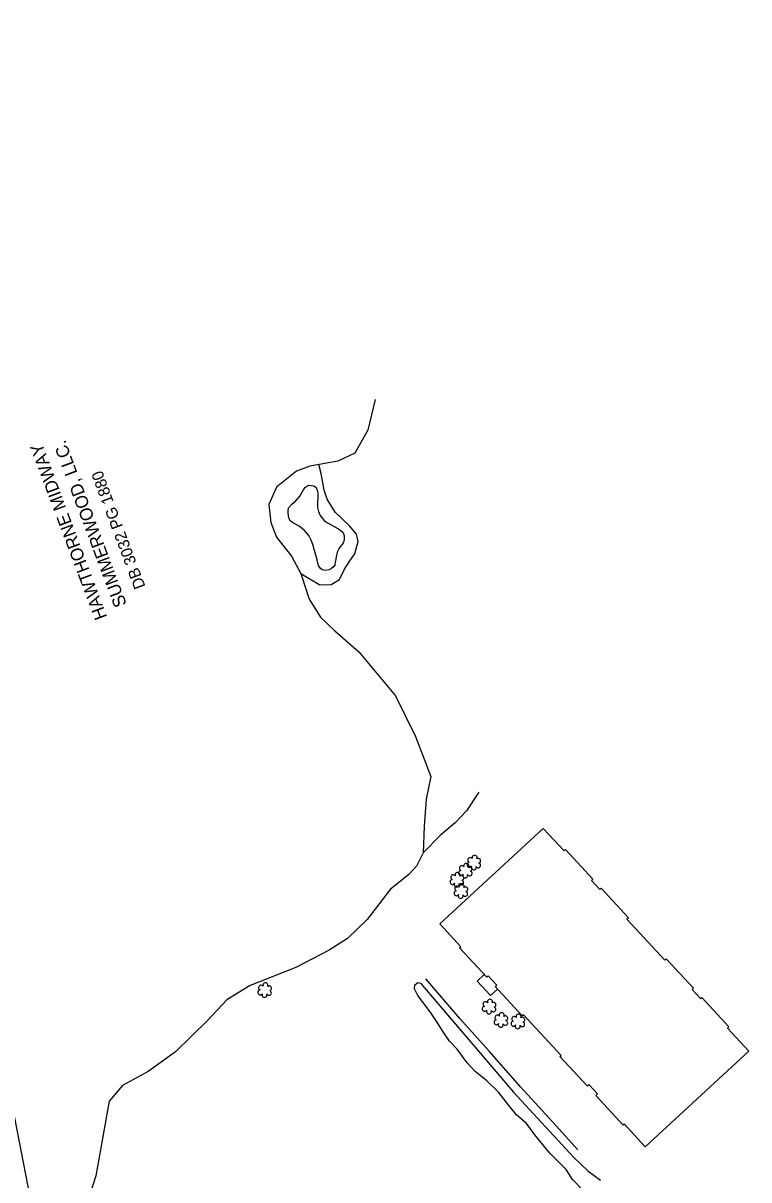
# Model space of a CAD drawing. Extents: x 1611576 to 1617186, y 899279 to 905462.
# Drawn here: x 1616361.3 to 1616645.4, y 903835.4 to 904288.3 of the extents above; entities that cross this region are included whole.
import ezdxf

# ---------------------------------------------------------------- set-up
doc = ezdxf.new("R2010")
doc.units = 0
for name, color, linetype in [('Exist Building', 7, 'Continuous'), ('Exist Other Culture Area Outline', 7, 'Continuous'), ('Exist Property Deed Book Text', 7, 'Continuous'), ('Exist Property Owner Text', 7, 'Continuous'), ('Exist Vegetation Hedge Row', 7, 'Continuous'), ('Exist Vegetation Shrub CELL', 7, 'Continuous'), ('Exist Vegetation Woods Line', 7, 'Continuous')]:
    doc.layers.add(name, color=color, linetype=linetype)

msp = doc.modelspace()

# ---------------------------------------------------------------- linework, layer by layer
at = {"layer": 'Exist Building'}
msp.add_lwpolyline([(1616645.44, 903885.78), (1616604.9, 903848.36), (1616596.66, 903857.28), (1616596.19, 903856.85), (1616585.49, 903868.45), (1616586.16, 903869.08), (1616582.89, 903872.63), (1616582.26, 903872.04), (1616571.49, 903883.71), (1616571.92, 903884.11), (1616557.21, 903900.05), (1616556.71, 903899.59), (1616546.07, 903911.11), (1616546.7, 903911.69), (1616543.39, 903915.27), (1616542.8, 903914.72), (1616532.18, 903926.23), (1616532.68, 903926.69), (1616524.44, 903935.63), (1616564.96, 903973.03), (1616573.06, 903964.25), (1616573.59, 903964.74), (1616584.34, 903953.09), (1616583.87, 903952.66), (1616587.13, 903949.13), (1616587.64, 903949.6), (1616598.3, 903938.04), (1616597.68, 903937.47), (1616612.48, 903921.42), (1616613.07, 903921.97), (1616623.74, 903910.41), (1616623.23, 903909.94), (1616626.58, 903906.32), (1616627.06, 903906.77), (1616637.66, 903895.28), (1616637.13, 903894.79)], close=True, dxfattribs=at)
msp.add_lwpolyline([(1616578.51, 903847.14), (1616569.84, 903856.72), (1616563.03, 903864.13), (1616555.97, 903871.79), (1616543.71, 903885.76), (1616532.29, 903898.62), (1616518.92, 903914.17)], dxfattribs=at)
at = {"layer": 'Exist Other Culture Area Outline'}
msp.add_lwpolyline([(1616476.65, 904102.98), (1616476.49, 904100.42), (1616476.54, 904098.64), (1616476.91, 904097.1), (1616477.59, 904095.58), (1616478.45, 904094.38), (1616479.34, 904093.41), (1616480.23, 904092.84), (1616481.24, 904092.29), (1616483.12, 904091.27), (1616484.75, 904090.36), (1616486.41, 904089.04), (1616486.74, 904088.47), (1616486.99, 904087.54), (1616486.95, 904086.53), (1616486.92, 904085.85), (1616486.61, 904084.78), (1616486.25, 904084.14), (1616485.67, 904083.61), (1616485.01, 904082.75), (1616484.27, 904081.13), (1616483.89, 904079.42), (1616483.77, 904078.37), (1616483.42, 904077.35), (1616483.28, 904076.15), (1616482.81, 904075.44), (1616482.08, 904074.79), (1616481.14, 904074.27), (1616479.66, 904074.05), (1616478.89, 904074.16), (1616478.33, 904074.28), (1616477.59, 904074.94), (1616476.98, 904075.92), (1616476.37, 904078.15), (1616475.38, 904081.88), (1616474.67, 904084.17), (1616474.05, 904085.93), (1616473.08, 904087.65), (1616471.48, 904089.65), (1616469.39, 904091.41), (1616467.16, 904092.53), (1616466, 904093.36), (1616465.47, 904094.19), (1616465.17, 904095.33), (1616464.99, 904096.72), (1616465.09, 904097.78), (1616465.3, 904098.64), (1616466.5, 904099.97), (1616467.87, 904101.12), (1616469.64, 904103.12), (1616471.18, 904105.87), (1616471.86, 904106.67), (1616472.61, 904107.17), (1616473.19, 904107.36), (1616474.11, 904107.32), (1616475.09, 904107.12), (1616475.75, 904106.68), (1616476.11, 904106.17), (1616476.6, 904105.02), (1616476.7, 904104.28), (1616476.71, 904103.33)], close=True, dxfattribs=at)
msp.add_lwpolyline([(1616546.98, 903910.12), (1616544.31, 903907.64), (1616539.09, 903913.26), (1616541.81, 903915.79)], dxfattribs=at)
at = {"layer": 'Exist Vegetation Hedge Row'}
for points in [[(1616469.99, 904072.86), (1616477.49, 904068.39), (1616481.83, 904068.54), (1616485.13, 904070.53), (1616487.1, 904074.59), (1616489.24, 904077.74), (1616491.2, 904080.59), (1616492.5, 904085.37), (1616491.82, 904088.27), (1616489.04, 904091.56), (1616483.42, 904096.9), (1616480.27, 904101.88), (1616479.13, 904105.52), (1616477.92, 904111.94), (1616477.08, 904115.48)], [(1616539.73, 903987.17), (1616534.9, 903979.95), (1616530.41, 903975.15), (1616524.87, 903970.45), (1616517.88, 903963.49)], [(1616580.58, 903831.2), (1616576.43, 903835.55), (1616573.97, 903839.45), (1616571.06, 903842.27), (1616567.46, 903845.79), (1616561.69, 903852.97), (1616558.36, 903857.48), (1616554.43, 903860.81), (1616551.06, 903864.98), (1616547.4, 903869.78), (1616542.84, 903874.17), (1616538.25, 903877.78), (1616535.16, 903881.22), (1616531.28, 903886.51), (1616528.28, 903889.77), (1616525.73, 903893.38), (1616522.81, 903897.88), (1616520.2, 903901.76), (1616515.81, 903907.54), (1616514.48, 903910.23), (1616514.69, 903911.76), (1616515.82, 903912.68), (1616516.86, 903912.42), (1616553.26, 903869.74), (1616576.92, 903844.21), (1616582.4, 903838.98), (1616587.33, 903835.33)]]:
    msp.add_lwpolyline(points, dxfattribs=at)
at = {"layer": 'Exist Vegetation Shrub CELL'}
for p, q in [((1616534.52, 903956.31), (1616534.52, 903956.31)), ((1616537.81, 903959.48), (1616537.81, 903959.48)), ((1616531.18, 903952.72), (1616531.18, 903952.72)), ((1616532.75, 903948.3), (1616532.75, 903948.3)), ((1616455.92, 903909.52), (1616455.92, 903909.52)), ((1616543.8, 903903.07), (1616543.8, 903903.07)), ((1616548.43, 903897.81), (1616548.43, 903897.81)), ((1616555.07, 903897.25), (1616555.07, 903897.25))]:
    msp.add_line(p, q, dxfattribs=at)
for centre, radius, start, end in [((1616536.33, 903960.61), 0.968, 35.8908, 245.4216), ((1616538.04, 903961.52), 0.99, 334.8391, 200.4717), ((1616539.49, 903960.35), 0.929, 284.4567, 126.0861), ((1616531.41, 903954.76), 0.99, 334.8391, 200.4717), ((1616532.72, 903955.6), 0.955, 95.1099, 327.9534), ((1616533.04, 903957.44), 0.968, 35.8908, 245.4216), ((1616534.75, 903958.35), 0.99, 334.8391, 200.4717), ((1616536.01, 903958.78), 0.955, 95.1099, 327.9534), ((1616536.16, 903955.38), 0.937, 204.9913, 73.4601), ((1616536.19, 903957.18), 0.929, 284.4567, 126.0861), ((1616537.69, 903957.8), 0.984, 151.2797, 21.387), ((1616539.45, 903958.55), 0.937, 204.9913, 73.4601), ((1616529.38, 903952.02), 0.955, 95.1099, 327.9534), ((1616529.7, 903953.85), 0.968, 35.8908, 245.4216), ((1616531.06, 903951.04), 0.984, 151.2797, 21.387), ((1616532.82, 903951.79), 0.937, 204.9913, 73.4601), ((1616532.98, 903950.34), 0.99, 334.8391, 200.4717), ((1616532.86, 903953.59), 0.929, 284.4567, 126.0861), ((1616534.39, 903954.63), 0.984, 151.2797, 21.387), ((1616530.95, 903947.59), 0.955, 95.1099, 327.9534), ((1616531.27, 903949.42), 0.968, 35.8908, 245.4216), ((1616532.62, 903946.61), 0.984, 151.2797, 21.387), ((1616534.39, 903947.37), 0.937, 204.9913, 73.4601), ((1616534.42, 903949.17), 0.929, 284.4567, 126.0861), ((1616454.43, 903910.64), 0.968, 35.8908, 245.4216), ((1616456.15, 903911.56), 0.99, 334.8391, 200.4717), ((1616457.59, 903910.39), 0.929, 284.4567, 126.0861), ((1616454.12, 903908.81), 0.955, 95.1099, 327.9534), ((1616455.79, 903907.83), 0.984, 151.2797, 21.387), ((1616457.55, 903908.59), 0.937, 204.9913, 73.4601), ((1616544.03, 903905.11), 0.99, 334.8391, 200.4717), ((1616542, 903902.36), 0.955, 95.1099, 327.9534), ((1616542.32, 903904.19), 0.968, 35.8908, 245.4216), ((1616543.67, 903901.38), 0.984, 151.2797, 21.387), ((1616545.44, 903902.14), 0.937, 204.9913, 73.4601), ((1616545.47, 903903.93), 0.929, 284.4567, 126.0861), ((1616546.63, 903897.1), 0.955, 95.1099, 327.9534), ((1616546.95, 903898.93), 0.968, 35.8908, 245.4216), ((1616548.66, 903899.85), 0.99, 334.8391, 200.4717), ((1616550.07, 903896.88), 0.937, 204.9913, 73.4601), ((1616550.1, 903898.67), 0.929, 284.4567, 126.0861), ((1616553.27, 903896.54), 0.955, 95.1099, 327.9534), ((1616553.58, 903898.38), 0.968, 35.8908, 245.4216), ((1616555.29, 903899.29), 0.99, 334.8391, 200.4717), ((1616556.7, 903896.32), 0.937, 204.9913, 73.4601), ((1616556.74, 903898.12), 0.929, 284.4567, 126.0861), ((1616548.3, 903896.12), 0.984, 151.2797, 21.387), ((1616554.94, 903895.57), 0.984, 151.2797, 21.387)]:
    msp.add_arc(centre, radius, start, end, dxfattribs=at)
at = {"layer": 'Exist Vegetation Woods Line'}
for points in [[(1616365.59, 903820.6), (1616353.15, 903884.59), (1616347.73, 903925.27), (1616338.73, 903963.54), (1616335.36, 903990.43), (1616333.66, 903998.74), (1616328.38, 904009.6), (1616321.8, 904021.23), (1616318.01, 904031.04), (1616304.54, 904095.81), (1616295.76, 904137.81), (1616284.29, 904196.22), (1616273.61, 904253.55), (1616273.63, 904261.89), (1616276.22, 904274.47), (1616277.23, 904281.08), (1616276.85, 904288.34)], [(1616499.15, 904140.95), (1616496.29, 904129.02), (1616491.21, 904119.89), (1616484.52, 904116.85), (1616473.49, 904114.83), (1616468.32, 904112.88), (1616460.43, 904106.61), (1616457.53, 904099.8), (1616458.23, 904092.84), (1616460.53, 904087.06), (1616466.33, 904079.57), (1616469.99, 904072.86), (1616473.29, 904062.76), (1616477.67, 904055.67), (1616483.3, 904050.36), (1616492.77, 904042.16), (1616507.06, 904024.93), (1616514.86, 904008.97), (1616520.87, 903993.31), (1616519.05, 903984.48), (1616518.32, 903973.96), (1616517.88, 903963.49), (1616515.25, 903958.17), (1616512.28, 903954.91), (1616505.04, 903949.04), (1616495.97, 903937.39), (1616488.22, 903929.92), (1616481.14, 903925.34), (1616468.11, 903918.5), (1616450.17, 903911.57), (1616441.1, 903905.83), (1616433.66, 903897.96), (1616420.98, 903885.51), (1616410.26, 903877.8), (1616400.24, 903872.31), (1616394.99, 903866.23), (1616389.74, 903837.01), (1616382.55, 903814.69)]]:
    msp.add_lwpolyline(points, dxfattribs=at)

# ---------------------------------------------------------------- texts
at = {"layer": 'Exist Property Deed Book Text'}
msp.add_text('DB 3032 PG 1880', height=4.5, rotation=110.55, dxfattribs=at).set_placement((1616409.24, 904067.75))
at = {"layer": 'Exist Property Owner Text'}
for s, p in [('SUMMERWOOD, LLC.', (1616401.92, 904060.73)), ('HAWTHORNE MIDWAY', (1616394.25, 904055.79))]:
    msp.add_text(s, height=5, rotation=110.55, dxfattribs=at).set_placement(p)

doc.saveas('drawing.dxf')
